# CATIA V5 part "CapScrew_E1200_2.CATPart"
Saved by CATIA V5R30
Part number: Sroub_M4x12
Nomenclature: E1200/4x12
Description: MEUSBURGER
Publications: "DrillHole", "TapHole", "Base"
Bounding box of the stored display mesh (mm): x -3.499 to 3.499, y -3.495 to 3.495, z -4 to 12
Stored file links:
  E:\Bakalarka\Model\Forma_v7\CapScrew_E1200_2.CATPart
  E:\dev\MoldDesign\intel_a\startup\components\MoldCatalog\CapScrew\Meusburger\CapScrew_E1200\TableE1200.txt
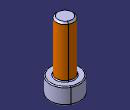
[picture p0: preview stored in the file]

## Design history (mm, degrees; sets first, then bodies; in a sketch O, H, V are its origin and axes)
Parameters
  Ref = "E1200/4x12" {design table}
  L = 12 mm {design table}
  D = 4 mm {design table}
  D1 = 4 mm {design table}
  D3 = 7 mm {design table}
  L1 = 12 mm {design table}
  L2 = 12 mm {design table}
  L3 = 4 mm {design table}
  SW = 3 mm {design table}
  dkren = 3.14 mm {design table}
  L4 = 2 mm {design table}
  R = 0.2 mm {design table}
  R1 = 0.4 mm {design table}
  F = 0.4 mm {design table}
  kdkern = 3.24 mm {design table}
  kd1 = 4.5 mm {design table}
  kl1 = 10 mm {design table}
  kd3 = 8 mm {design table}
  kl3 = 4.5 mm {design table}
  kl = 20.5 mm {design table}
  c = 4 mm {design table}
  ThreadString = "M4" {design table}
  Mat = "" {design table}
  HeatTreat = "" {design table}
  SupplierRef = "Meusburger 2017"
  BmpRef = "F_MldCapScrewLD"
  DrillHole_Length = 225 mm
  HeadThick = 4 mm {= L3}
  HeadDiam = 7 mm {= D3}
  ScrewThread = 12 mm {= Thread1.Depth}
  ScrewPitch = 0.7 mm {= Thread1.Pitch}
Set1 "BaseBody"
  Point1 "Base": (0, 0, 0)
  Plane1: type Offset, RefPlane xy-plane, Offset 225 {= DrillHole_Length}, reversed
Body1 "PartBody" (main body)
  Sketch1 on yz-plane, origin (0, 0, 0), H (0, 0, -1), V (0, 1, 0)
    point P1 (4, 0)
    line L1 (4, 0) -> (4, -3.5)
    line L2 (4, -3.5) -> (0, -3.5)
    line L3 (0, -3.5) -> (0, -2)
    point P5 (0, -2)
    line L4 (0, -2) -> (-12, -2)
    line L5 (-12, -2) -> (-12, 0)
    point P7 (-12, 0)
    axis line L6 (-12, 0) -> (4, 0)
    point P8 (4, 0)
    construction line L7 (0, -2) -> (0, -2)
    line L8 (0, 0) -> (-12, 0)
    point P9 (-12, -2)
    point P10 (-12, -2)
    line L9 (0, 0) -> (4, 0)
    length L1 = 3.5 {= D3 /2}
    distance L1 L3 = 4 {= L3}
    distance L4 L6 = 2 {= D /2}
    distance L3 L5 = 12 {= L}
    distance L5 P5 = 12 {= L1}
    coincidence: P1 L6, L6 H, P8 L1, P9 P10, P7 L5, L3 V
    vertical: L1 V, L3 V, L5 V
    horizontal: L2 H, L4 H, L7 H, L8 H, L9 H
  Shaft1: profile Sketch1, axis Sketch1.L6, angle 360
  Sketch2 on face of Shaft1 from Sketch1.L1, origin (0, 0, -4), H (1, 0, 0), V (0, -1, 0)
    point P1 (-0.866, -1.5)
    point P2 (0.866, -1.5)
    point P3 (1.7321, 0)
    point P4 (0.866, 1.5)
    point P5 (-0.866, 1.5)
    point P6 (-1.7321, 0)
    point P7 (0, -1.5)
    line L1 (-0.866, -1.5) -> (0.866, -1.5)
    line L2 (0.866, -1.5) -> (1.7321, 0)
    line L3 (1.7321, 0) -> (0.866, 1.5)
    line L4 (0.866, 1.5) -> (-0.866, 1.5)
    line L5 (-0.866, 1.5) -> (-1.7321, 0)
    line L6 (-1.7321, 0) -> (-0.866, -1.5)
    construction line L7 (0, 0) -> (0, -1.5)
    construction circle A1 centre (0, 0) radius 1.7321
    construction arc A2 centre (-0.866, 1.5) radius 1.7321 from (0.866, 1.5) to (-1.7321, 0) cw
    construction arc A3 centre (0.866, -1.5) radius 1.7321 from (1.7321, 0) to (-0.866, -1.5) ccw
    point P8 (-0.866, 1.5)
    point P9 (0.866, -1.5)
    distance L1 L4 = 3 {= SW}
    coincidence: A1 P1, A1 P2, A1 P3, A1 P4, A1 P5, A1 P6, A2 P4, A2 P6, A2 O, P8 P5, A3 P3, A3 P1, A3 O, P9 P2, P3 H
    midpoint: P7 L1
  Pocket1: profile Sketch2, direction (0, 0, 1), length 2 {= L4}
  Thread1: "M4", diameter 4, depth 12 {= L2}, pitch 0.7, on face of Shaft1 from Sketch1.L4, from face of Shaft1 from Sketch1.L5
  Fillet1: radius 0.4 {= R1}, on edge [face of Shaft1 from Sketch1.L2 | face of Shaft1 from Sketch1.L1]
  Fillet2: radius 0.2 {= R}, on edge [face of Shaft1 from Sketch1.L3 | face of Shaft1 from Sketch1.L2]
  Fillet3: radius 0.2 {= R}, on edge [face of Shaft1 from Sketch1.L4 | face of Shaft1 from Sketch1.L3]
  Chamfer1: length 0.4 {= F}, angle 45, on edge [face of Shaft1 from Sketch1.L5 | face of Shaft1 from Sketch1.L4]
Body2 "DrillHole"
  Sketch3 on Plane1, origin (22.3066, -22.3066, -225), H (1, 0, 0), V (0, 1, 0)
    point P1 (-22.3066, 22.3066)
    reference projected circle E1 centre (-22.3066, 22.3066) radius 3.5 from edge [face of Shaft1 from Sketch1.L3 | face of Shaft1 from Sketch1.L2]
    concentricity: E1 P1
  Hole1: placed by Sketch3, at (0, 0, -225) direction (0, 0, 1), diameter 4.5 {= kd1}, depth 237 {= DrillHole_Length +L1}, counterbore diameter 8 {= kd3}, counterbore depth 225 {= DrillHole_Length}
Body3 "TapHole"
  Sketch4 on Plane1, origin (0, 0, -225), H (1, 0, 0), V (0, 1, 0)
    point P1 (0, 0)
    reference projected point E1 (0, 0) from Point1
    coincidence: E1 P1
  Hole2: placed by Sketch4, at (0, 0, -225) direction (0, 0, 1), diameter 3.242, depth 245.5 {= DrillHole_Length +kl}, V-bottom angle 120, threaded "M4", thread diameter 4, thread depth 245.5 {= DrillHole_Length +kl}, pitch 0.7
Relations
  design table "TableE1200", configuration 22, drives Ref, L, D, D1, D3, L1, L2, L3, SW, dkren, L4, R, R1, F, kdkern, kd1, kl1, kd3, kl3, kl, c, ThreadString, Mat, HeatTreat
  Thread1.ThreadDescription = ThreadString
  Hole2.ThreadDescription = ThreadString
